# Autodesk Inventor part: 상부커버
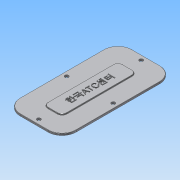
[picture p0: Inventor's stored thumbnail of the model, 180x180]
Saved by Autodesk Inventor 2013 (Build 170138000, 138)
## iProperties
Created: 2016-02
Part Number: 상부커버
Material: 알루미늄 6061
Document SubType Name: Modeling
Designer: mduedu
Density: 2.71 g/cm^3
Mass: 42.0587 g
Surface Area: 149.263 cm^2
Volume: 15.5198 cm^3
Author: mduedu
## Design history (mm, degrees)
sketch "스케치1"
  geometry: L1 (30, 60)-(-30, 60); L2 (-30, 60)-(-30, -60); L3 (-30, -60)-(30, -60); L4 (30, -60)-(30, 60); L5 (30, 60)-(-30, -60); L6 (-30, 60)-(30, -60); 1 further point
  constraints: 12 end point, 2 midpoint, 2 parallel, 1 horizontal, 1 perpendicular
  dimensions: "d0" = 60 distance of L2.end L3.end; "d2" = 120 distance of L1.end L2.end
extrude "돌출1" new body sketch "스케치1" distance "d3" = 2; taper "d4" = 0 deg
fillet "모깎기1" dims "d5" = 15
sketch "스케치2"
  geometry: L1 (30, 45)-(30, -45) reference; L2 (15, -60)-(-15, -60) reference; L3 (-30, -45)-(-30, 45) reference; L4 (-15, 60)-(15, 60) reference; L5 (25, 45)-(25, -45); L6 (15, -55)-(-15, -55); L7 (-25, -45)-(-25, 45); L8 (-15, 55)-(15, 55); A1 r 15 centre (15, 45) between (30, 45) and (15, 60) reference; A2 r 15 centre (15, -45) between (15, -60) and (30, -45) reference; A3 r 15 centre (-15, -45) between (-30, -45) and (-15, -60) reference; A4 r 15 centre (-15, 45) between (-15, 60) and (-30, 45) reference; A5 r 10 centre (15, 45) between (25, 45) and (15, 55); A6 r 10 centre (15, -45) between (15, -55) and (25, -45); A7 r 10 centre (-15, -45) between (-25, -45) and (-15, -55); A8 r 10 centre (-15, 45) between (-15, 55) and (-25, 45); 4 further points
  constraints: 8 end point, 8 point on circle, 4 centre point, 4 midpoint, 7 other
  dimensions: "d8" = 5 distance between parallel lines of L7 L3
hole "구멍1" sketch "스케치2" at (0, 55), (25, 0), (0, -55), (-25, 0) diameter "d9" = 4; stored, may be unused: countersink angle "d13" = 90 deg, drill point angle "d15" = 118 deg; dims "d10" = 6, "d11" = 4, "d12" = 2, "d14" = 8
sketch "스케치3"
  geometry: L1 (10, -40)-(-10, -40); L2 (-10, -40)-(-10, 40); L3 (-10, 40)-(10, 40); L4 (10, 40)-(10, -40); L5 (10, -40)-(-10, 40); L6 (-10, -40)-(10, 40); 1 further point
  constraints: 12 end point, 2 midpoint, 2 parallel, 1 horizontal, 1 perpendicular
  dimensions: "d16" = 80 distance of L1.end L2.end; "d18" = 20 distance of L2.end L3.end
extrude "돌출2" join sketch "스케치3" distance "d19" = 1; taper "d20" = 0 deg
fillet "모깎기2" dims "d21" = 5
fillet "모깎기3" dims "d22" = 0.3
fillet "모깎기4" dims "d23" = 0.3
sketch "스케치4"
  geometry: 2 further points
  constraints: 1 coincident, 1 other
feature "엠보싱1" sketch "스케치4" dims "d0" = 60, "d2" = 120, "d8" = 5, "d24" = 0.5, "d25" = 0
node "솔리드1"
node "절단 모서리 투영1"
